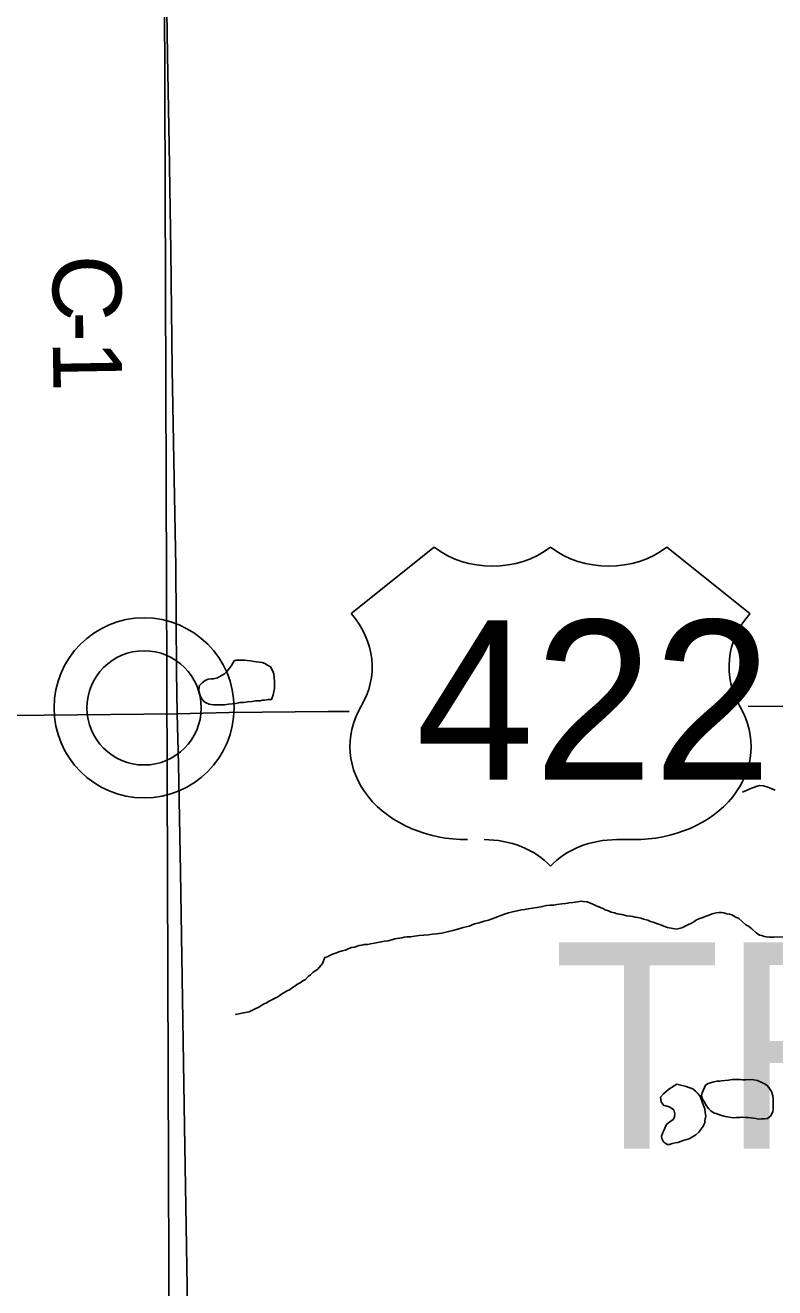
# Model space of a CAD drawing. Extents: x -10.1 to 68, y -9.5 to 29.2.
# Drawn here: x 7.37 to 7.989, y 19.13 to 20.173 of the extents above; entities that cross this region are included whole.
import ezdxf

# ---------------------------------------------------------------- set-up
doc = ezdxf.new("R2010")
doc.units = 0
for name, color, linetype in [('GM_X_County_Road', 7, 'Continuous'), ('GM_X_County_Road_Text', 7, 'Continuous'), ('GM_X_Minor_Lake', 7, 'Continuous'), ('GM_X_Minor_River', 7, 'Continuous'), ('GM_X_Section', 7, 'Continuous'), ('GM_X_Township_Text', 7, 'Continuous'), ('GM_X_Unincorporated', 7, 'Continuous'), ('GM_X_US_Route', 7, 'Continuous'), ('GM_X_US_Shield', 7, 'Continuous')]:
    doc.layers.add(name, color=color, linetype=linetype)

msp = doc.modelspace()

# ---------------------------------------------------------------- linework, layer by layer
at = {"layer": 'GM_X_County_Road'}
for points in [[(7.4745, 20.9), (7.4753, 20.8576), (7.4762, 20.8102), (7.4781, 20.7182), (7.4795, 20.6284), (7.4825, 20.4461), (7.4843, 20.3365), (7.4853, 20.2561), (7.4871, 20.1482), (7.4885, 20.0736), (7.4899, 19.9865), (7.491, 19.8885), (7.4927, 19.7979), (7.494, 19.7256), (7.4945, 19.6385), (7.495, 19.6038)], [(7.495, 19.6038), (7.4962, 19.5624), (7.4978, 19.473), (7.501, 19.2631), (7.5047, 19.0477), (7.5089, 18.8338), (7.5108, 18.7383), (7.5113, 18.6856), (7.513, 18.6303), (7.5141, 18.5902), (7.5161, 18.4613), (7.5177, 18.3096), (7.5197, 18.1709), (7.5217, 17.9835), (7.5233, 17.8668), (7.524, 17.8111), (7.5251, 17.7267), (7.5267, 17.614), (7.5273, 17.5492), (7.5298, 17.379), (7.5318, 17.1984), (7.5343, 17.0271), (7.5359, 16.8846)]]:
    msp.add_lwpolyline(points, dxfattribs=at)
at = {"layer": 'GM_X_Minor_Lake'}
for points in [[(7.5423, 19.6475), (7.5401, 19.6437), (7.5383, 19.6414), (7.536, 19.6387), (7.5342, 19.6367), (7.5285, 19.6336), (7.5251, 19.6327), (7.5232, 19.6327), (7.5206, 19.6323), (7.5183, 19.6314), (7.5157, 19.6295), (7.5135, 19.6272), (7.5131, 19.6241), (7.5132, 19.6218), (7.514, 19.6188), (7.5148, 19.6169), (7.5172, 19.6139), (7.5191, 19.6128), (7.5214, 19.6117), (7.5233, 19.6114), (7.5252, 19.6111), (7.5279, 19.6111), (7.5309, 19.6112), (7.5343, 19.6113), (7.5374, 19.6117), (7.5435, 19.6122), (7.5469, 19.6131), (7.5499, 19.6131), (7.5533, 19.6136), (7.5571, 19.614), (7.5598, 19.6145), (7.5617, 19.6145), (7.5636, 19.6146), (7.5655, 19.615), (7.5674, 19.615), (7.5704, 19.6155), (7.5731, 19.6155), (7.5745, 19.6194), (7.5755, 19.6247), (7.5755, 19.6274), (7.5754, 19.6304), (7.5753, 19.6338), (7.5749, 19.6365), (7.5741, 19.6391), (7.5721, 19.6425), (7.5698, 19.644), (7.5675, 19.6454), (7.5652, 19.6461), (7.5583, 19.6471), (7.556, 19.6475), (7.553, 19.6478), (7.5507, 19.6481), (7.5488, 19.6481), (7.5465, 19.648), (7.5438, 19.648), (7.5423, 19.6475)], [(7.5423, 19.6475), (7.5401, 19.6437), (7.5383, 19.6414), (7.536, 19.6387), (7.5342, 19.6367), (7.5285, 19.6336), (7.5251, 19.6327), (7.5232, 19.6327), (7.5206, 19.6323), (7.5183, 19.6314), (7.5157, 19.6295), (7.5135, 19.6272), (7.5131, 19.6241), (7.5132, 19.6218), (7.514, 19.6188), (7.5148, 19.6169), (7.5172, 19.6139), (7.5191, 19.6128), (7.5214, 19.6117), (7.5233, 19.6114), (7.5252, 19.6111), (7.5279, 19.6111), (7.5309, 19.6112), (7.5343, 19.6113), (7.5374, 19.6117), (7.5435, 19.6122), (7.5469, 19.6131), (7.5499, 19.6131)], [(7.5499, 19.6131), (7.5533, 19.6136), (7.5571, 19.614), (7.5598, 19.6145), (7.5617, 19.6145), (7.5636, 19.6146), (7.5655, 19.615), (7.5674, 19.615), (7.5704, 19.6155), (7.5731, 19.6155), (7.5745, 19.6194), (7.5755, 19.6247), (7.5755, 19.6274), (7.5754, 19.6304), (7.5753, 19.6338), (7.5749, 19.6365), (7.5741, 19.6391), (7.5721, 19.6425), (7.5698, 19.644), (7.5675, 19.6454), (7.5652, 19.6461), (7.5583, 19.6471), (7.556, 19.6475), (7.553, 19.6478), (7.5507, 19.6481), (7.5488, 19.6481), (7.5465, 19.648), (7.5438, 19.648), (7.5423, 19.6475)], [(7.9792, 19.2987), (7.9746, 19.3008), (7.9715, 19.3012), (7.9681, 19.3015), (7.9651, 19.3014), (7.9624, 19.3013), (7.9605, 19.3017), (7.9575, 19.3016), (7.954, 19.3015), (7.9506, 19.3011), (7.9449, 19.3006), (7.943, 19.3002), (7.9411, 19.3001), (7.9385, 19.2997), (7.9358, 19.2989), (7.9339, 19.2984), (7.9317, 19.2969), (7.9299, 19.293), (7.9288, 19.2907), (7.9285, 19.2881), (7.9293, 19.2854), (7.9309, 19.2828), (7.9324, 19.2798), (7.9344, 19.2775), (7.936, 19.2757), (7.9387, 19.2738), (7.9406, 19.2735), (7.944, 19.2721)], [(7.9792, 19.2987), (7.9746, 19.3008), (7.9715, 19.3012), (7.9681, 19.3015), (7.9651, 19.3014), (7.9624, 19.3013), (7.9605, 19.3017), (7.9575, 19.3016), (7.954, 19.3015), (7.9506, 19.3011), (7.9449, 19.3006), (7.943, 19.3002), (7.9411, 19.3001), (7.9385, 19.2997), (7.9358, 19.2989), (7.9339, 19.2984), (7.9317, 19.2969), (7.9299, 19.293), (7.9288, 19.2907), (7.9285, 19.2881), (7.9293, 19.2854), (7.9309, 19.2828), (7.9324, 19.2798), (7.9344, 19.2775), (7.936, 19.2757), (7.9387, 19.2738), (7.9406, 19.2735), (7.944, 19.2721), (7.9459, 19.2717), (7.9478, 19.271), (7.9498, 19.2707), (7.9528, 19.2703), (7.9551, 19.27), (7.9574, 19.2701), (7.96, 19.2701), (7.9619, 19.2705), (7.965, 19.2702), (7.9669, 19.2703), (7.9734, 19.2693), (7.9757, 19.2689), (7.9779, 19.269), (7.9802, 19.269), (7.9829, 19.2695), (7.9855, 19.2714), (7.9873, 19.2749), (7.9877, 19.2772), (7.9876, 19.2795), (7.9875, 19.2821), (7.9875, 19.2855), (7.9874, 19.2882), (7.9862, 19.2916), (7.9839, 19.295), (7.9823, 19.2968), (7.98, 19.2983), (7.9792, 19.2987)], [(7.9081, 19.2978), (7.9013, 19.2936), (7.8991, 19.2916), (7.8969, 19.2897), (7.8946, 19.2869), (7.8947, 19.285), (7.8951, 19.2832), (7.8971, 19.2802), (7.899, 19.2798), (7.9016, 19.2791), (7.9036, 19.278), (7.9055, 19.2765), (7.9063, 19.2731), (7.906, 19.2705), (7.9049, 19.2685), (7.9023, 19.2666), (7.8997, 19.2646), (7.8986, 19.2627), (7.8975, 19.26), (7.8964, 19.2577), (7.8953, 19.2547), (7.8957, 19.2528), (7.8969, 19.2501), (7.9, 19.2479), (7.9019, 19.248), (7.9042, 19.2488), (7.9065, 19.2492), (7.9087, 19.2496), (7.911, 19.2504), (7.914, 19.2516), (7.9163, 19.2521), (7.9182, 19.2525), (7.9238, 19.256), (7.9261, 19.258), (7.9279, 19.2603), (7.9298, 19.263), (7.9312, 19.2657), (7.9312, 19.2676), (7.9319, 19.2714), (7.9314, 19.2744), (7.931, 19.2775), (7.9301, 19.2801), (7.9289, 19.2831), (7.9277, 19.2861), (7.9269, 19.288), (7.925, 19.2903), (7.9234, 19.2921), (7.9211, 19.294), (7.918, 19.2951), (7.9157, 19.2958)], [(7.9157, 19.2958), (7.9081, 19.2978)], [(7.944, 19.2721), (7.9459, 19.2717), (7.9478, 19.271), (7.9498, 19.2707), (7.9528, 19.2703), (7.9551, 19.27), (7.9574, 19.2701), (7.96, 19.2701), (7.9619, 19.2705), (7.965, 19.2702), (7.9669, 19.2703), (7.9734, 19.2693), (7.9757, 19.2689), (7.9779, 19.269), (7.9802, 19.269), (7.9829, 19.2695), (7.9855, 19.2714), (7.9873, 19.2749), (7.9877, 19.2772), (7.9876, 19.2795), (7.9875, 19.2821), (7.9875, 19.2855), (7.9874, 19.2882), (7.9862, 19.2916), (7.9839, 19.295), (7.9823, 19.2968), (7.98, 19.2983), (7.9792, 19.2987)]]:
    msp.add_lwpolyline(points, dxfattribs=at)
at = {"layer": 'GM_X_Minor_River'}
for points in [[(7.9893, 19.5406), (7.9858, 19.542), (7.9831, 19.5431), (7.9797, 19.5442), (7.9763, 19.5445), (7.9744, 19.5441), (7.9721, 19.5432), (7.9691, 19.542), (7.9661, 19.5408), (7.9627, 19.5392), (7.9623, 19.5391)], [(7.9534, 19.4376), (7.9515, 19.4383), (7.9492, 19.4386), (7.9469, 19.4393), (7.945, 19.4397), (7.9431, 19.4396), (7.9405, 19.4392), (7.9371, 19.4384), (7.934, 19.4372), (7.9314, 19.4363), (7.9295, 19.4355), (7.9269, 19.4347), (7.9242, 19.4335), (7.922, 19.432), (7.9201, 19.4308), (7.9175, 19.4296), (7.9148, 19.4284), (7.9122, 19.4268), (7.9099, 19.4264), (7.9076, 19.4259), (7.9004, 19.4273), (7.8973, 19.4284), (7.8939, 19.4298), (7.892, 19.4302), (7.8885, 19.4316), (7.8862, 19.4323), (7.8839, 19.4334), (7.8805, 19.4341), (7.8785, 19.4348), (7.8755, 19.4355), (7.8736, 19.4358), (7.8717, 19.4362), (7.8698, 19.4365), (7.8667, 19.4368), (7.8625, 19.4379), (7.8606, 19.4382), (7.8587, 19.4386), (7.8564, 19.4393), (7.8537, 19.44), (7.8514, 19.4411), (7.8487, 19.4418), (7.8468, 19.4429), (7.8449, 19.4436), (7.8426, 19.4447), (7.8403, 19.4458), (7.838, 19.4468), (7.8357, 19.4476), (7.8338, 19.4483), (7.8307, 19.4486), (7.8288, 19.4489), (7.8258, 19.4485), (7.822, 19.448), (7.8189, 19.4476), (7.8163, 19.4471), (7.8129, 19.4467), (7.8087, 19.4462), (7.806, 19.4458), (7.8034, 19.4457), (7.8003, 19.4453), (7.7958, 19.4444), (7.7924, 19.4436), (7.7886, 19.4431), (7.7852, 19.4427), (7.7825, 19.4422), (7.7795, 19.4418), (7.7761, 19.4409), (7.7723, 19.4401), (7.7689, 19.4393), (7.7655, 19.4381), (7.7625, 19.4372), (7.7598, 19.436), (7.7553, 19.4344), (7.7523, 19.4332), (7.7489, 19.4324), (7.747, 19.432), (7.7447, 19.4311), (7.7409, 19.4303), (7.7364, 19.4283), (7.7315, 19.4271), (7.727, 19.4258), (7.7228, 19.4246), (7.7194, 19.4238), (7.7137, 19.4225), (7.7095, 19.422), (7.7058, 19.4216), (7.7027, 19.4211), (7.6989, 19.421), (7.6951, 19.4206), (7.6913, 19.4201), (7.6879, 19.4196), (7.6849, 19.4196), (7.6826, 19.4192), (7.6807, 19.4187), (7.6788, 19.4183), (7.675, 19.4178), (7.6724, 19.417), (7.6693, 19.4162), (7.6663, 19.4158), (7.6637, 19.4153), (7.661, 19.4149), (7.658, 19.4144)], [(7.9964, 19.4195), (7.9881, 19.4193), (7.9846, 19.4192), (7.982, 19.4196), (7.9801, 19.4199), (7.9781, 19.4206), (7.9762, 19.421), (7.9735, 19.4228), (7.97, 19.4262), (7.9673, 19.4284), (7.965, 19.4295), (7.9619, 19.4321), (7.9592, 19.4347), (7.9561, 19.4361), (7.9534, 19.4376)], [(7.658, 19.4144), (7.6549, 19.4136), (7.6523, 19.4132), (7.6496, 19.4131), (7.6477, 19.4127), (7.6455, 19.4123), (7.6417, 19.411), (7.639, 19.4106), (7.6368, 19.4098), (7.6341, 19.4086), (7.6315, 19.4078), (7.6288, 19.407), (7.6266, 19.4062), (7.6235, 19.4053), (7.619, 19.403), (7.6171, 19.4025), (7.6153, 19.3976), (7.6113, 19.3929), (7.6075, 19.3902), (7.6053, 19.3882), (7.6034, 19.3867), (7.6012, 19.3843), (7.5989, 19.3831), (7.5967, 19.3816), (7.594, 19.38), (7.5922, 19.3788), (7.5903, 19.3776), (7.5884, 19.3761), (7.5854, 19.3745), (7.5828, 19.3729), (7.5805, 19.3717), (7.5783, 19.3698), (7.5756, 19.3686), (7.5738, 19.3678), (7.5711, 19.3662), (7.5689, 19.365), (7.567, 19.3642), (7.5651, 19.363), (7.5621, 19.3611), (7.5602, 19.3602), (7.5568, 19.3587), (7.5546, 19.3575), (7.55, 19.3566), (7.5459, 19.3558), (7.5436, 19.3553), (7.5436, 19.3557), (7.5436, 19.3553)]]:
    msp.add_lwpolyline(points, dxfattribs=at)
at = {"layer": 'GM_X_Section'}
for points in [[(6.4939, 20.1965), (7.4845, 20.1996), (7.4884, 19.0658), (6.4989, 19.0557)], [(7.4845, 20.1996), (8.4385, 20.206), (8.4635, 19.0757), (7.4884, 19.0658)]]:
    msp.add_lwpolyline(points, close=True, dxfattribs=at)
at = {"layer": 'GM_X_Unincorporated'}
for radius in [0.0744, 0.0472]:
    msp.add_circle((7.4677, 19.6087), radius, dxfattribs=at)
at = {"layer": 'GM_X_US_Route'}
msp.add_line((7.9669, 19.6097), (7.998, 19.6101), dxfattribs=at)
msp.add_lwpolyline([(6.7538, 19.4732), (6.7778, 19.4809), (6.8145, 19.4929), (6.962, 19.5398), (6.9989, 19.552), (7.0324, 19.5613), (7.0685, 19.5691), (7.1608, 19.5887), (7.209, 19.5975), (7.2219, 19.5992), (7.2339, 19.6006), (7.2439, 19.6006), (7.2669, 19.6014), (7.3245, 19.6023), (7.3851, 19.6028), (7.495, 19.6038), (7.538, 19.6048), (7.6198, 19.6056), (7.6373, 19.6058)], dxfattribs=at)
at = {"layer": 'GM_X_US_Shield'}
for p, q in [((7.7075, 19.7416), (7.6388, 19.6866)), ((7.9684, 19.6866), (7.8997, 19.7416)), ((7.8585, 19.4999), (7.8723, 19.4999))]:
    msp.add_line(p, q, dxfattribs=at)
for centre, major_axis, start_param, end_param in [((7.7555, 19.7808), (-0.0687, 0), 0.795399, 2.346194), ((7.8517, 19.7808), (-0.0687, 0), 0.795399, 2.346194), ((7.5601, 19.6425), (0.0961, 0), 5.838949, 6.894067), ((8.0472, 19.6425), (-0.0961, 0), 5.672304, 6.727422), ((7.7339, 19.5768), (0.0961, 0), 2.702327, 4.723529), ((7.8733, 19.5768), (-0.0961, 0), 1.559657, 3.580859), ((7.7487, 19.4449), (-0.0687, 0), 3.785094, 4.712389), ((7.8585, 19.4449), (-0.0687, 0), 4.712389, 5.639684)]:
    msp.add_ellipse(centre, major_axis=major_axis, ratio=0.8, start_param=start_param, end_param=end_param, dxfattribs=at)

# ---------------------------------------------------------------- texts
at = {"layer": 'GM_X_County_Road_Text'}
for s, rotation, p in [('C', 270.0117, (7.3922, 19.9831)), ('-', 270.1544, (7.3922, 19.9363)), ('1', 271.0014, (7.3922, 19.9121))]:
    msp.add_text(s, height=0.0568, rotation=rotation, dxfattribs=at).set_placement(p)
at = {"layer": 'GM_X_Township_Text'}
msp.add_text('TROY', height=0.17045, rotation=0, dxfattribs=at).set_placement((7.8054, 19.2444))
at = {"layer": 'GM_X_US_Shield'}
msp.add_text('422', height=0.13184, dxfattribs=at).set_placement((7.6922, 19.5493))

doc.saveas('drawing.dxf')
